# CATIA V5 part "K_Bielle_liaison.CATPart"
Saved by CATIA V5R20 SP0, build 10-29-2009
Part number: Bielle_liaison
Bounding box of the stored display mesh (mm): x -95 to -16, y 114.524 to 176.898, z -141.841 to -100.687
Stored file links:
  G:\Khaled_CFAO_2011\ST2M\ST2M_GR2\plakomicki\Khaled\CAD_ThinkMOTION\K_Bielle_liaison.CATPart
  G:\Khaled_CFAO_2011\ST2M\ST2M_GR2\plakomicki\Khaled\CAD_ThinkMOTION\K_Jambe.CATProduct
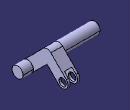
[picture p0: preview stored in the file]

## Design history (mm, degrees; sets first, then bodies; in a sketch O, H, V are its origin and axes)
Set1
  Plane1: linked copy from another document
  Point1 to Point3: linked copy from another document
  Plane2: linked copy from another document
Body1 (main body)
  Sketch1 on Plane1, origin (-38, 0, 0), H (0, 1, 0), V (0, 0, 1)
    construction line L1 (148.1873, -108.1873) -> (122.0244, -134.3503)
    point P1 (148.1873, -108.1873)
    point P2 (122.0244, -134.3503)
    line L2 (153.4906, -113.4906) -> (127.3277, -139.6536)
    line L3 (116.7211, -129.047) -> (142.884, -102.884)
    arc A1 centre (122.0244, -134.3503) radius 7.5 from (127.3277, -139.6536) to (116.7211, -129.047) cw
    arc A2 centre (148.1873, -108.1873) radius 7.5 from (142.884, -102.884) to (153.4906, -113.4906) cw
    reference projected point E1 (148.1873, -108.1873) from Point1
    reference projected point E2 (122.0244, -134.3503) from Point2
    distance L1 L2 = 7.5
    tangency: A1 L2, A2 L2, A1 L3, A2 L3
    coincidence: P1 E1, E2 P2
  Pad1: profile Sketch1, direction (1, 0, 0), length 8, mirrored extent
  Sketch2 on end face of Pad1, origin (-30, 0, 0), H (0, 1, 0), V (0, 0, 1)
    circle A1 centre (122.0244, -134.3503) radius 7.5
    point P1 (122.0244, -134.3503)
    reference projected point E1 (122.0244, -134.3503) from Point2
    radius A1 = 7.5
    coincidence: P1 E1
  Pad2: profile Sketch2, direction (1, 0, 0), length 14, opposite side length 30
  Sketch3 on start face of Pad1, origin (-46, 0, 0), H (0, -1, 0), V (0, 0, 1)
    circle A1 centre (-148.1873, -108.1873) radius 7.5
    point P1 (-148.1873, -108.1873)
    reference projected point E1 (-148.1873, -108.1873) from Point1
    radius A1 = 7.5
    coincidence: P1 E1
  Pad3: profile Sketch3, direction (-1, 0, 0), length 49
  Sketch4 on end face of Pad1, origin (-30, 0, 0), H (0, 1, 0), V (0, 0, 1)
    construction line L1 (148.1873, -108.1873) -> (169.4005, -129.4005)
    point P1 (148.1873, -108.1873)
    point P2 (169.4005, -129.4005)
    line L2 (153.4906, -102.884) -> (174.7038, -124.0972)
    line L3 (164.0972, -134.7038) -> (142.884, -113.4906)
    arc A1 centre (169.4005, -129.4005) radius 7.5 from (174.7038, -124.0972) to (164.0972, -134.7038) cw
    arc A2 centre (148.1873, -108.1873) radius 7.5 from (142.884, -113.4906) to (153.4906, -102.884) cw
    reference projected point E1 (148.1873, -108.1873) from Point1
    reference projected point E2 (169.4005, -129.4005) from Point3
    circle A3 centre (169.4005, -129.4005) radius 5
    distance L1 L2 = 7.5
    radius A3 = 5
    tangency: A1 L2, A2 L2, A1 L3, A2 L3
    coincidence: E1 P1, E2 P2
  Pad4: profile Sketch4, direction (-1, 0, 0), length 16
  Sketch5 on Plane2, origin (0, 149.4005, -149.4005), H (-1, 0, 0), V (0, 0.7071, 0.7071)
    line L1 (33, 37) -> (43, 37)
    line L2 (43, 37) -> (43, 16)
    line L3 (43, 16) -> (33, 16)
    line L4 (33, 16) -> (33, 37)
    horizontal: L1 H, L3 H
    vertical: L2 V, L4 V
  Pocket1: profile Sketch5, direction (0, -0.7071, 0.7071), length 8, mirrored extent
